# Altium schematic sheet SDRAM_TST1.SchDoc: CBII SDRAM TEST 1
size A3; Engineer: showell; DocumentNumber: 1; Revision: 1.1; SheetNumber: 1; SheetTotal: 1
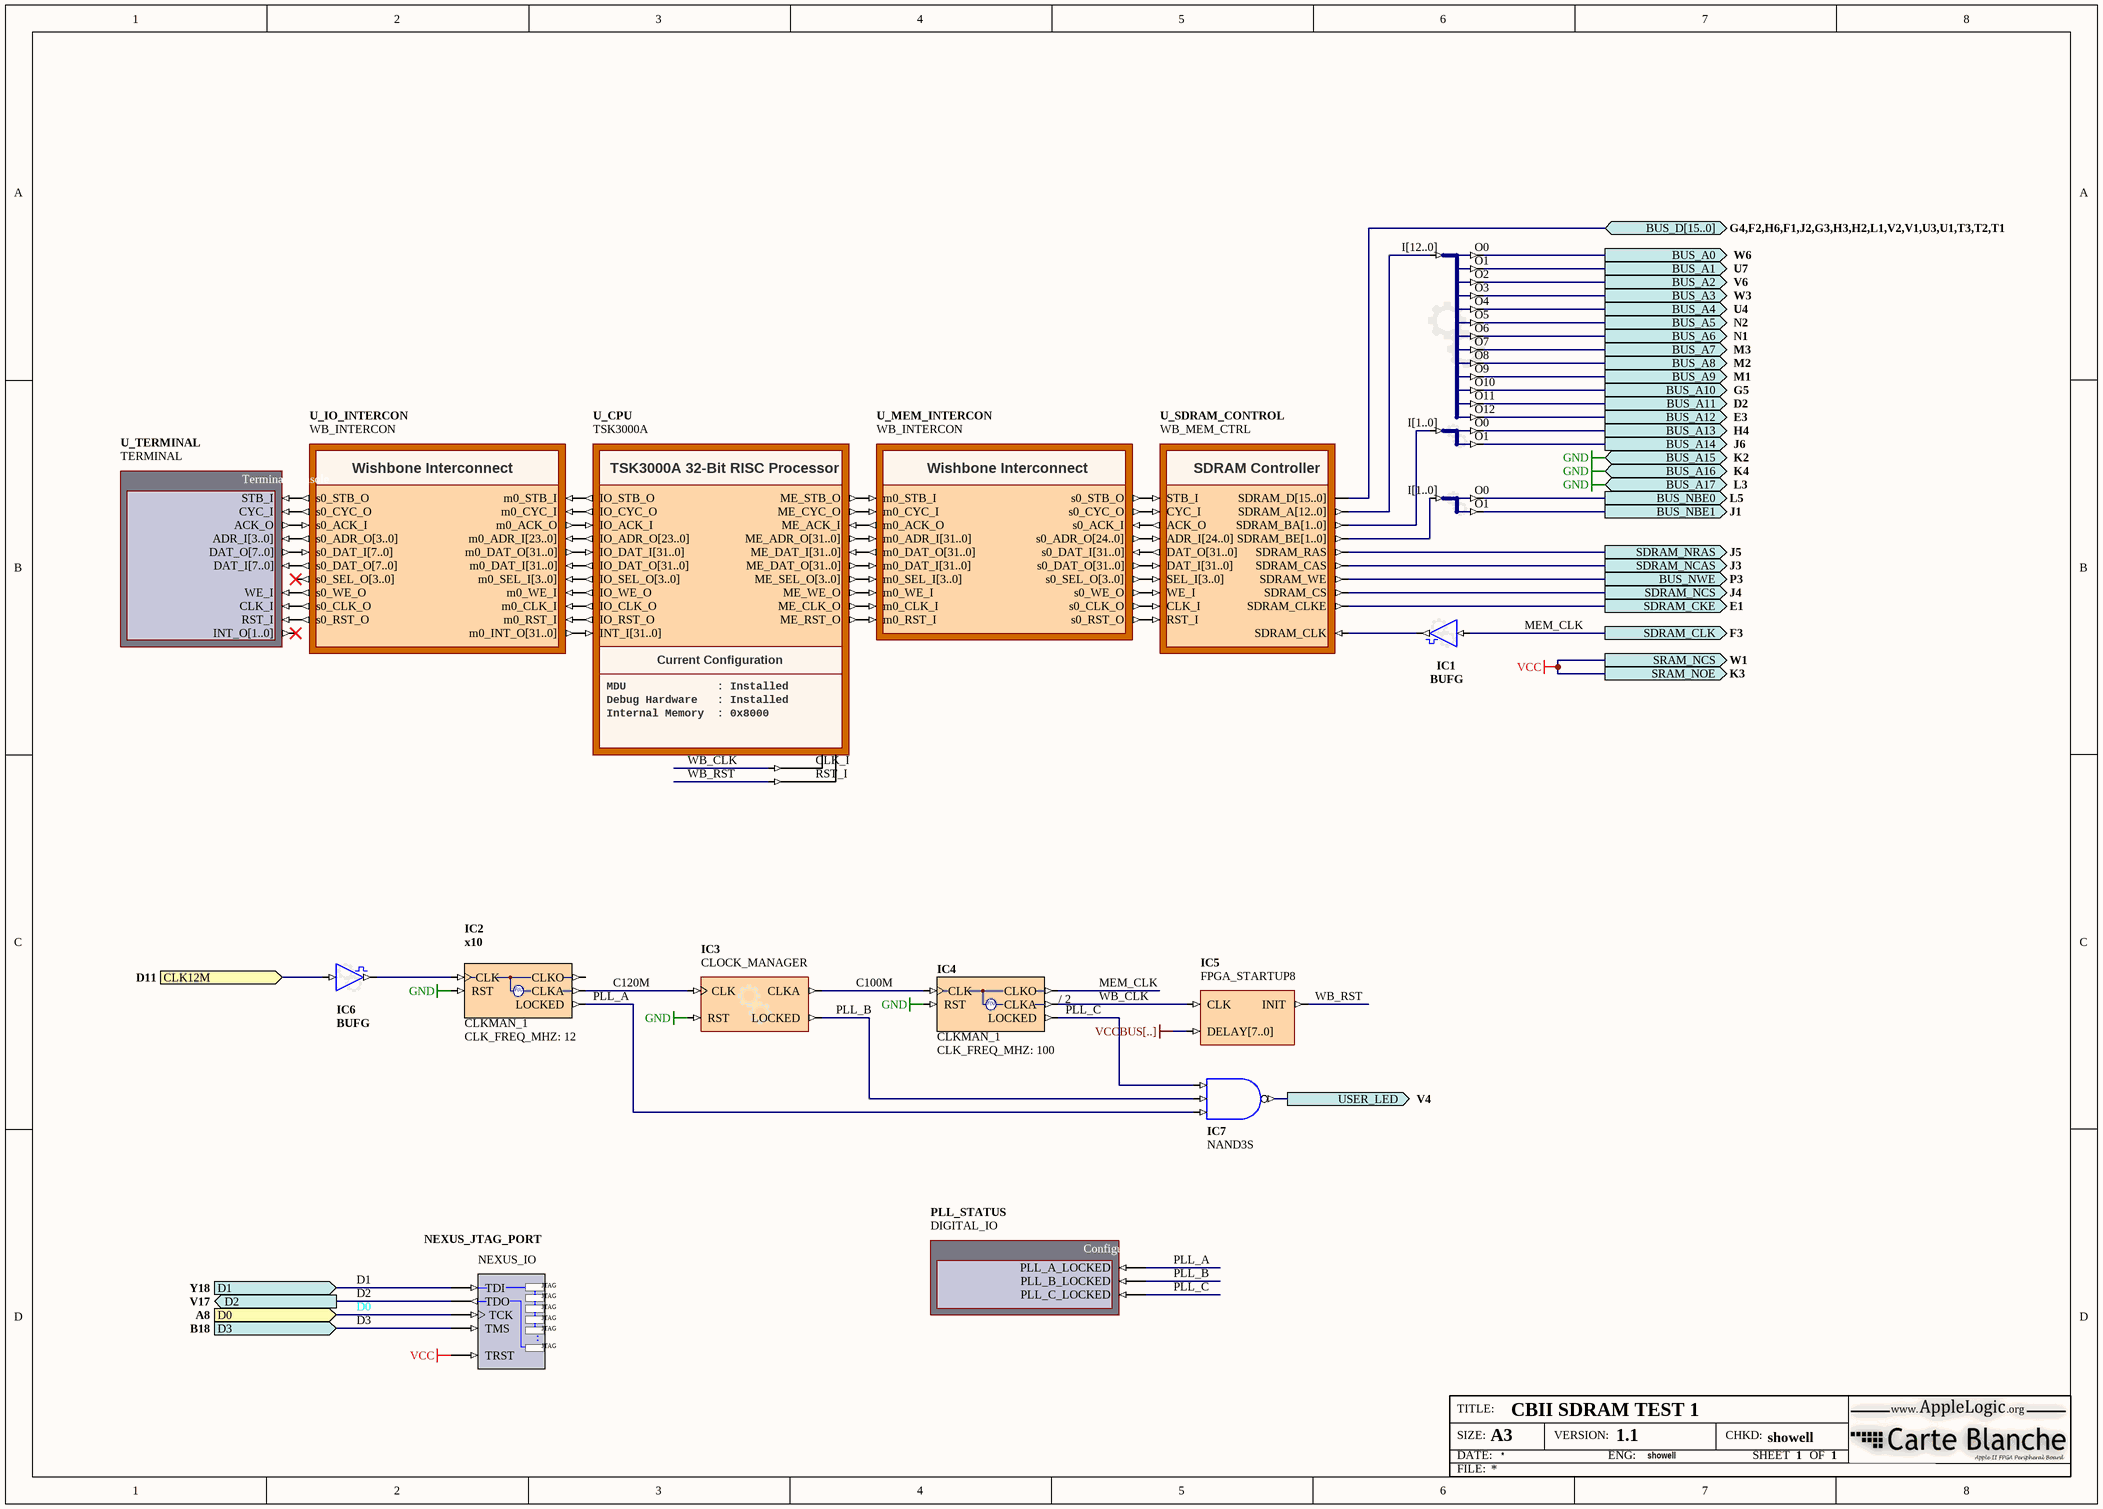
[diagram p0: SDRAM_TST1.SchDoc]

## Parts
IC1  BUFG
IC2  CLKMAN_1  CLK_FREQ_MHZ: 12  ClkA_Operation: x10
IC3  CLOCK_MANAGER
IC4  CLKMAN_1  CLK_FREQ_MHZ: 100  ClkA_Operation: / 2
IC5  FPGA_STARTUP8
IC6  BUFG
IC7  NAND3S
NEXUS_JTAG_PORT  NEXUS_IO
PLL_STATUS  DIGITAL_IO
U1011  BUS_JS  (value not drawn)
U1018  BUS_JS  (value not drawn)
U8011  BUS_JS  (value not drawn)
U_CPU  TSK3000A
U_IO_INTERCON  WB_INTERCON
U_MEM_INTERCON  WB_INTERCON
U_SDRAM_CONTROL  WB_MEM_CTRL
U_TERMINAL  TERMINAL

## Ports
BUS_A0 (out, see W6), BUS_A1 (out, see U7), BUS_A2 (out, see V6), BUS_A3 (out, see W3), BUS_A4 (out, see U4), BUS_A5 (out, see N2), BUS_A6 (out, see N1), BUS_A7 (out, see M3), BUS_A8 (out, see M2), BUS_A9 (out, see M1), BUS_A10 (out, see G5), BUS_A11 (out, see D2), BUS_A12 (out, see E3), BUS_A13 (out, see H4), BUS_A14 (out, see J6), BUS_A15 (out, see K2), BUS_A16 (out, see K4), BUS_A17 (out, see L3), BUS_D[15..0] (bidir, see G4,F2,H6,F1,J2,G3,H3,H2,L1,V2,V1,U3,U1,T3,T2,T1), BUS_NBE0 (out, see L5), BUS_NBE1 (out, see J1), BUS_NWE (out, see P3), CLK12M (in, see D11), D0 (in, see A8), D1 (in, see Y18), D2 (out, see V17), D3 (in, see B18), SDRAM_CKE (out, see E1), SDRAM_CLK (out, see F3), SDRAM_NCAS (out, see J3), SDRAM_NCS (out, see J4), SDRAM_NRAS (out, see J5), SRAM_NCS (out, see W1), SRAM_NOE (out, see K3), USER_LED (out, see V4)

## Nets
GND: IC2.RST IC3.RST IC4.RST ; port BUS_A15, port BUS_A16, port BUS_A17
VCC: NEXUS_JTAG_PORT.TRST ; port SRAM_NOE, port SRAM_NCS
BUS_A0: U1018.O0 ; port BUS_A0
BUS_A1: U1018.O1 ; port BUS_A1
BUS_A2: U1018.O2 ; port BUS_A2
BUS_A3: U1018.O3 ; port BUS_A3
BUS_A4: U1018.O4 ; port BUS_A4
BUS_A5: U1018.O5 ; port BUS_A5
BUS_A6: U1018.O6 ; port BUS_A6
BUS_A7: U1018.O7 ; port BUS_A7
BUS_A8: U1018.O8 ; port BUS_A8
BUS_A9: U1018.O9 ; port BUS_A9
BUS_A10: U1018.O10 ; port BUS_A10
BUS_A11: U1018.O11 ; port BUS_A11
BUS_A12: U1018.O12 ; port BUS_A12
BUS_A13: U8011.O0 ; port BUS_A13
BUS_A14: U8011.O1 ; port BUS_A14
BUS_NBE0: U1011.O0 ; port BUS_NBE0
BUS_NBE1: U1011.O1 ; port BUS_NBE1
BUS_NWE: U_SDRAM_CONTROL.SDRAM_WE ; port BUS_NWE
C100M: IC3.CLKA IC4.CLK
C120M: IC2.CLKA IC3.CLK
CLK12M: IC6.I ; port CLK12M
D0: NEXUS_JTAG_PORT.TCK ; port D0
D1: NEXUS_JTAG_PORT.TDI ; port D1
D2: NEXUS_JTAG_PORT.TDO ; port D2
D3: NEXUS_JTAG_PORT.TMS ; port D3
MEM_CLK: IC1.I IC4.CLKO ; port SDRAM_CLK
PLL_A: IC2.LOCKED IC7.I0 PLL_STATUS.PLL_A_LOCKED
PLL_B: IC3.LOCKED IC7.I1 PLL_STATUS.PLL_B_LOCKED
PLL_C: IC4.LOCKED IC7.I2 PLL_STATUS.PLL_C_LOCKED
SDRAM_CKE: U_SDRAM_CONTROL.SDRAM_CLKE ; port SDRAM_CKE
SDRAM_NCAS: U_SDRAM_CONTROL.SDRAM_CAS ; port SDRAM_NCAS
SDRAM_NCS: U_SDRAM_CONTROL.SDRAM_CS ; port SDRAM_NCS
SDRAM_NRAS: U_SDRAM_CONTROL.SDRAM_RAS ; port SDRAM_NRAS
USER_LED: IC7.O ; port USER_LED
WB_CLK: IC4.CLKA IC5.CLK U_CPU.CLK_I
WB_RST: IC5.INIT U_CPU.RST_I
NetIC1_O: IC1.O U_SDRAM_CONTROL.SDRAM_CLK
NetIC2_CLK: IC2.CLK IC6.O
NetU_CPU_INT_I[31..0]: U_CPU.INT_I[31..0] U_IO_INTERCON.m0_INT_O[31..0]
NetU_CPU_IO_ACK_I: U_CPU.IO_ACK_I U_IO_INTERCON.m0_ACK_O
NetU_CPU_IO_ADR_O[23..0]: U_CPU.IO_ADR_O[23..0] U_IO_INTERCON.m0_ADR_I[23..0]
NetU_CPU_IO_CLK_O: U_CPU.IO_CLK_O U_IO_INTERCON.m0_CLK_I
NetU_CPU_IO_CYC_O: U_CPU.IO_CYC_O U_IO_INTERCON.m0_CYC_I
NetU_CPU_IO_DAT_I[31..0]: U_CPU.IO_DAT_I[31..0] U_IO_INTERCON.m0_DAT_O[31..0]
NetU_CPU_IO_DAT_O[31..0]: U_CPU.IO_DAT_O[31..0] U_IO_INTERCON.m0_DAT_I[31..0]
NetU_CPU_IO_RST_O: U_CPU.IO_RST_O U_IO_INTERCON.m0_RST_I
NetU_CPU_IO_SEL_O[3..0]: U_CPU.IO_SEL_O[3..0] U_IO_INTERCON.m0_SEL_I[3..0]
NetU_CPU_IO_STB_O: U_CPU.IO_STB_O U_IO_INTERCON.m0_STB_I
NetU_CPU_IO_WE_O: U_CPU.IO_WE_O U_IO_INTERCON.m0_WE_I
NetU_CPU_ME_ACK_I: U_CPU.ME_ACK_I U_MEM_INTERCON.m0_ACK_O
NetU_CPU_ME_ADR_O[31..0]: U_CPU.ME_ADR_O[31..0] U_MEM_INTERCON.m0_ADR_I[31..0]
NetU_CPU_ME_CLK_O: U_CPU.ME_CLK_O U_MEM_INTERCON.m0_CLK_I
NetU_CPU_ME_CYC_O: U_CPU.ME_CYC_O U_MEM_INTERCON.m0_CYC_I
NetU_CPU_ME_DAT_I[31..0]: U_CPU.ME_DAT_I[31..0] U_MEM_INTERCON.m0_DAT_O[31..0]
NetU_CPU_ME_DAT_O[31..0]: U_CPU.ME_DAT_O[31..0] U_MEM_INTERCON.m0_DAT_I[31..0]
NetU_CPU_ME_RST_O: U_CPU.ME_RST_O U_MEM_INTERCON.m0_RST_I
NetU_CPU_ME_SEL_O[3..0]: U_CPU.ME_SEL_O[3..0] U_MEM_INTERCON.m0_SEL_I[3..0]
NetU_CPU_ME_STB_O: U_CPU.ME_STB_O U_MEM_INTERCON.m0_STB_I
NetU_CPU_ME_WE_O: U_CPU.ME_WE_O U_MEM_INTERCON.m0_WE_I
NetU_IO_INTERCON_s0_ACK_I: U_IO_INTERCON.s0_ACK_I U_TERMINAL.ACK_O
NetU_IO_INTERCON_s0_ADR_O[3..0]: U_IO_INTERCON.s0_ADR_O[3..0] U_TERMINAL.ADR_I[3..0]
NetU_IO_INTERCON_s0_CLK_O: U_IO_INTERCON.s0_CLK_O U_TERMINAL.CLK_I
NetU_IO_INTERCON_s0_CYC_O: U_IO_INTERCON.s0_CYC_O U_TERMINAL.CYC_I
NetU_IO_INTERCON_s0_DAT_I[7..0]: U_IO_INTERCON.s0_DAT_I[7..0] U_TERMINAL.DAT_O[7..0]
NetU_IO_INTERCON_s0_DAT_O[7..0]: U_IO_INTERCON.s0_DAT_O[7..0] U_TERMINAL.DAT_I[7..0]
NetU_IO_INTERCON_s0_RST_O: U_IO_INTERCON.s0_RST_O U_TERMINAL.RST_I
NetU_IO_INTERCON_s0_STB_O: U_IO_INTERCON.s0_STB_O U_TERMINAL.STB_I
NetU_IO_INTERCON_s0_WE_O: U_IO_INTERCON.s0_WE_O U_TERMINAL.WE_I
NetU_MEM_INTERCON_s0_ACK_I: U_MEM_INTERCON.s0_ACK_I U_SDRAM_CONTROL.ACK_O
NetU_MEM_INTERCON_s0_ADR_O[24..0]: U_MEM_INTERCON.s0_ADR_O[24..0] U_SDRAM_CONTROL.ADR_I[24..0]
NetU_MEM_INTERCON_s0_CLK_O: U_MEM_INTERCON.s0_CLK_O U_SDRAM_CONTROL.CLK_I
NetU_MEM_INTERCON_s0_CYC_O: U_MEM_INTERCON.s0_CYC_O U_SDRAM_CONTROL.CYC_I
NetU_MEM_INTERCON_s0_DAT_I[31..0]: U_MEM_INTERCON.s0_DAT_I[31..0] U_SDRAM_CONTROL.DAT_O[31..0]
NetU_MEM_INTERCON_s0_DAT_O[31..0]: U_MEM_INTERCON.s0_DAT_O[31..0] U_SDRAM_CONTROL.DAT_I[31..0]
NetU_MEM_INTERCON_s0_RST_O: U_MEM_INTERCON.s0_RST_O U_SDRAM_CONTROL.RST_I
NetU_MEM_INTERCON_s0_SEL_O[3..0]: U_MEM_INTERCON.s0_SEL_O[3..0] U_SDRAM_CONTROL.SEL_I[3..0]
NetU_MEM_INTERCON_s0_STB_O: U_MEM_INTERCON.s0_STB_O U_SDRAM_CONTROL.STB_I
NetU_MEM_INTERCON_s0_WE_O: U_MEM_INTERCON.s0_WE_O U_SDRAM_CONTROL.WE_I

Not connected (* = marked no-connect by the designer): IC2 CLKO; IC5 DELAY[7..0]; U1011 I[1..0]; U1018 I[12..0]; U8011 I[1..0]; U_IO_INTERCON s0_SEL_O[3..0]*; U_SDRAM_CONTROL SDRAM_A[12..0] SDRAM_BA[1..0] SDRAM_BE[1..0] SDRAM_D[15..0]; U_TERMINAL INT_O[1..0]*

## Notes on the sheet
- Labels drawn without touching a wire or pin: VCCBUS[..]

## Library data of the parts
IC1 IC6 = BUFG: Configurable Global Clock Buffer; ConfiguratorName: GENERIC_BUFFER; ConfigurationParameters: {}Version[1.1]{}SignalCount[1]{}SignalWidth0[1]{}OutputOption0[Global Clock]{}EnableMode[None]{}ShowPinNames[False]{}
IC2 IC4 = CLKMAN_1: Single Operational Output Clock Manager; Clk_Count: 1
IC3 = CLOCKMANAGER: Configurable Clock Manager; ConfiguratorName: GENERIC_CLOCKMANAGER; ConfigurationParameters: {}Version[1.0]{}Option_Configuration[object _1: TClockManagerPersist / VersionMajor [ 0 / VersionMinor [ 0 / InputFreq [ 120.000000000000000000 / InputName [ 'CLK' / OutputTargets [ < / item / Name [ 'CLKA' / OutFreqMin [ 100.000000000000000000 / OutFreqMax [ 100.000000000000000000 / OutPostDivider [ 1.000000000000000000 / end> / OutputDevices [ < / item / Name [ 'Spartan3AN' / Valid [ True / OutputActuals [ < / item / Name [ 'CLK0' / Multipler [ 1.000000000000000000 / Divider [ 1.000000000000000000 / OutFreq [ 120.000000000000000000 / OutputMap [ 1 / end / item / Name [ 'CLK90' / Multipler [ 1.000000000000000000 / Divider [ 1.000000000000000000 / OutPhase [ 90.000000000000000000 / OutFreq [ 120.000000000000000000 / OutputMap [ 2 / end / item / Name [ 'CLK180' / Multipler [ 1.000000000000000000 / Divider [ 1.000000000000000000 / OutPhase [ 180.000000000000000000 / OutFreq [ 120.000000000000000000 / OutputMap [ 3 / end / item / Name [ 'CLK270' / Multipler [ 1.000000000000000000 / Divider [ 1.000000000000000000 / OutPhase [ 270.000000000000000000 / OutFreq [ 120.000000000000000000 / OutputMap [ 4 / end / item / Name [ 'CLK2X' / Multipler [ 2.000000000000000000 / Divider [ 1.000000000000000000 / OutFreq [ 240.000000000000000000 / OutputMap [ 5 / end / item / Name [ 'CLKDV' / Multipler [ 1.000000000000000000 / Divider [ 16.000000000000000000 / OutFreq [ 7.500000000000000000 / OutputMap [ 6 / end / item / Name [ 'CLK2X180' / Multipler [ 1.000000000000000000 / Divider [ 1.000000000000000000 / OutPhase [ 180.000000000000000000 / OutFreq [ 240.000000000000000000 / OutputMap [ 7 / end / item / Name [ 'CLKFX' / Multipler [ 5.000000000000000000 / Divider [ 6.000000000000000000 / OutFreq [ 100.000000000000000000 / OutputMap [ 0 / end / item / Name [ 'CLKFX180' / Multipler [ 1.000000000000000000 / Divider [ 1.000000000000000000 / OutPhase [ 180.000000000000000000 / OutFreq [ 100.000000000000000000 / OutputMap [ 8 / end> / InternalActuals [ <> / CustomVars [ <> / end> / MinInputFreq [ 1.000000000000000000 / MaxInputFreq [ 280.000000000000000000 / MinOutputFreq [ 18.000000000000000000 / MaxOutputFreq [ 210.000000000000000000 / MaxOutputCount [ 9 / end]{}
IC5 = FPGA_STARTUP8: FPGA Startup With 8 Bit Delay
IC7 = NAND3: 3-Input NAND Gate, Single Pin Version; ArchiveName: GENERIC; XilinxEquivalent: NAND3; FunctionalClass: Logic Primitive; PortSize: 3; VHDLIB_SIM: GENERIC_LIB
NEXUS_JTAG_PORT = NEXUS_JTAG_PORT: Soft Nexus-Chain Connector; NEXUS_JTAG_CONNECTOR: True
PLL_STATUS = DIGITAL_IO: Configurable Digital IO; NEXUS_CORE: Instrument; NEXUS_JTAG_DEVICE: True; NEXUS_JTAG_ORDER: 0; ConfigurationParameters: {}Version[2.0]{}StorageType[3]{}InterfaceType[Parallel]{}SchCompWidth[140]{}Input0Name[PLL_A_LOCKED]{}Input0Width[1]{}Input0InitValue[0]{}Input0Kind[LEDs]{}Input0LEDStyle[Green]{}Input1Name[PLL_B_LOCKED]{}Input1Width[1]{}Input1InitValue[0]{}Input1Kind[LEDs]{}Input1LEDStyle[Green]{}Input2Name[PLL_C_LOCKED]{}Input2Width[1]{}Input2InitValue[0]{}Input2Kind[LEDs]{}Input2LEDStyle[Green]{}NoOutputs[ ]{}Designator[LED]{}InternalID[0]{}
U1011 U8011 = BUS_JS: Configurable Bus Joiner/Splitter; ConfiguratorName: GENERIC_BUS_JS; ConfigurationParameters: {}Version[1.1]{}SplitterJoinerType[Splitter]{}SignalCount[2]{}SignalWidth0[1]{}GapBelow0[1000000]{}ConnectionType0[Pin]{}SignalWidth1[1]{}GapBelow1[1000000]{}ConnectionType1[Pin]{}ShowPinNames[True]{}
U1018 = BUS_JS: Configurable Bus Joiner/Splitter; ConfiguratorName: GENERIC_BUS_JS; ConfigurationParameters: {}Version[1.1]{}SplitterJoinerType[Splitter]{}SignalCount[13]{}SignalWidth0[1]{}GapBelow0[1000000]{}ConnectionType0[Pin]{}SignalWidth1[1]{}GapBelow1[1000000]{}ConnectionType1[Pin]{}SignalWidth2[1]{}GapBelow2[1000000]{}ConnectionType2[Pin]{}SignalWidth3[1]{}GapBelow3[1000000]{}ConnectionType3[Pin]{}SignalWidth4[1]{}GapBelow4[1000000]{}ConnectionType4[Pin]{}SignalWidth5[1]{}GapBelow5[1000000]{}ConnectionType5[Pin]{}SignalWidth6[1]{}GapBelow6[1000000]{}ConnectionType6[Pin]{}SignalWidth7[1]{}GapBelow7[1000000]{}ConnectionType7[Pin]{}SignalWidth8[1]{}GapBelow8[1000000]{}ConnectionType8[Pin]{}SignalWidth9[1]{}GapBelow9[1000000]{}ConnectionType9[Pin]{}SignalWidth10[1]{}GapBelow10[1000000]{}ConnectionType10[Pin]{}SignalWidth11[1]{}GapBelow11[1000000]{}ConnectionType11[Pin]{}SignalWidth12[1]{}GapBelow12[1000000]{}ConnectionType12[Pin]{}ShowPinNames[True]{}
U_CPU = TSK3000A: TSK3000A OCD Microprocessor; Nexus_JTAG_Device: True; Nexus_Core: Processor_OCDS; Nexus_JTAG_Order: 0; ConfigurationParameters: {}Version[1.1]{}Option_Processor[0]{}Option_Memory[5]{}Option_ExactMemory[32K]{}Option_MDU[0]{}Option_OCDS[0]{}Option_Shifter[0]{}Option_InterruptCount[32]{}Option_DebugWhenReset[0]{}; ConfiguratorName: FPGA_MCU32; Memory_Configuration: Record[AUTOIMPORT]{}AutoImport_Peripherals[False]{}AutoImport_Memory[False]{n}Record[CODE_EXPORT]{}ExportType[1]{n}Record[NEXUS_CORE]{}ComponentDesignator[MCU]{}Memory_Depth[32768]{}Memory_UsageType[nvram]{}Memory_Configuration[]{}Memory_External[False]{}Memory_Speed[1]{}ProgramDownloadAddress[0x0]{}Memory_BusType[TSK3000:addr_bus]{}Memory_Mau[8]{}Memory_MatchedComponent[]{}Memory_Description[]{}Memory_FillBitPattern[]{}Memory_IncludeDependencies[False]{}Memory_ByLoadAddress[False]{}Memory_CopyDuringInit[False]{}Memory_NoCopyDuringInit[False]{}Memory_Interrupts[]{n}Record[NEXUS_CORE]{}ComponentDesignator[XMEM]{}Memory_Depth[0x2000000]{}Memory_UsageType[ram]{}Memory_Configuration[]{}Memory_External[False]{}Memory_Speed[4]{}ProgramDownloadAddress[0x01000000]{}Memory_BusType[TSK3000:addr_bus]{}Memory_Mau[8]{}Memory_MatchedComponent[]{}Memory_Description[INTERCON_MEM]{}Memory_FillBitPattern[]{}Memory_IncludeDependencies[False]{}Memory_ByLoadAddress[False]{}Memory_CopyDuringInit[False]{}Memory_NoCopyDuringInit[False]{}Memory_Interrupts[]{n}Record[PERIPHERAL]{}ComponentDesignator[SOFT_TERMINAL]{}Memory_Depth[0x0010]{}Memory_UsageType[peripheral]{}Memory_Configuration[]{}Memory_External[False]{}Memory_Speed[1]{}ProgramDownloadAddress[0xFF000000]{}Memory_BusType[TSK3000:addr_bus]{}Memory_Mau[8]{}Memory_MatchedComponent[]{}Memory_Description[INTERCON_IO]{}Memory_FillBitPattern[]{}Memory_IncludeDependencies[False]{}Memory_ByLoadAddress[False]{}Memory_CopyDuringInit[False]{}Memory_NoCopyDuringInit[False]{}Memory_Interrupts[]{n}Record[PHYSICAL_MEMORY]{}ComponentDesignator[MCU]{}Memory_Depth[32768]{}Memory_UsageType[nvram]{}Memory_Configuration[]{}Memory_External[False]{}Memory_Speed[1]{}ProgramDownloadAddress[0x0]{}Memory_BusType[TSK3000:addr_bus]{}Memory_Mau[8]{}Memory_MatchedComponent[]{}Memory_Description[]{}Memory_FillBitPattern[]{}Memory_IncludeDependencies[False]{}Memory_ByLoadAddress[False]{}Memory_CopyDuringInit[False]{}Memory_NoCopyDuringInit[False]{}Memory_Interrupts[]{n}Record[PHYSICAL_MEMORY]{}ComponentDesignator[XMEM]{}Memory_Depth[0x2000000]{}Memory_UsageType[ram]{}Memory_Configuration[]{}Memory_External[False]{}Memory_Speed[4]{}ProgramDownloadAddress[0x01000000]{}Memory_BusType[TSK3000:addr_bus]{}Memory_Mau[8]{}Memory_MatchedComponent[]{}Memory_Description[INTERCON_MEM]{}Memory_FillBitPattern[]{}Memory_IncludeDependencies[False]{}Memory_ByLoadAddress[False]{}Memory_CopyDuringInit[False]{}Memory_NoCopyDuringInit[False]{}Memory_Interrupts[]{n}; ChildModel1: TSK3000A_MCU; ChildModel2: TSK3000A_MDU; ChildModel3: TSK3000A_OCDS; ChildModel4: TSK3000A_Shift_Barrel; ChildModel5: TSK3000A_Shift_Sequential; ChildModel6: Mult_32x32; ChildModel7: m33x33
U_IO_INTERCON = WB_INTERCON: Configurable Wishbone Interconnect; ConfigurationParameters: {}Version[1.0]{}UnusedInterrupts[1]{}MasterAddressBits[1]{}Name0[SOFT_TERMINAL]{}Kind0[0]{}SpaceAfter0[4]{}Address_Base0[0]{}Address_Bits0[4]{}Address_Mode0[1]{}Address_DecodeWidth0[8]{}DataWidth0[2]{}UsedInterrupts0[ ]
U_MEM_INTERCON = WB_INTERCON: Configurable Wishbone Interconnect; ConfigurationParameters: {}Version[1.0]{}UnusedInterrupts[2]{}MasterAddressBits[0]{}Name0[XRAM]{}Kind0[2]{}SpaceAfter0[4]{}Address_Base0[16777216]{}Address_Bits0[25]{}Address_Mode0[1]{}Address_DecodeWidth0[6]{}DataWidth0[0]{}UsedInterrupts0[ ]
U_SDRAM_CONTROL = WB_MEM_CTRL: Configurable Memory Controller; ConfigurationParameters: {}Version[2.0]{}Option_MemoryType[Synchronous DRAM]{}Option_MemorySize[32 MB (8M x 32-bit)]{}Option_Layout[1 x 16-bit Wide Device]{}Option_Read[2]{}Option_WriteSetup[1]{}Option_WritePulse[1]{}Option_WriteHold[1]{}Option_FlashRead[4]{}Option_FlashWriteSetup[1]{}Option_FlashWritePulse[5]{}Option_FlashWriteHold[1]{}Option_SdramKeepRowOpen[0]{}Option_SdramClock[100]{}Option_SdramWriteRecovery[2]{}Option_SdramAutoRefresh[7]{}Option_SdramActiveToReadWrite[2]{}Option_SdramPrecharge[2]{}Option_SdramCasLatency[2]{}Option_SdramClockScheme[0]{}Option_SdramModeRegister[2]{}Option_SdramCache[False]{}Option_SdramRefreshTime[0]{}
U_TERMINAL = TERMINAL: Instrument Terminal (Wishbone); NEXUS_JTAG_DEVICE: True; NEXUS_JTAG_ORDER: 0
